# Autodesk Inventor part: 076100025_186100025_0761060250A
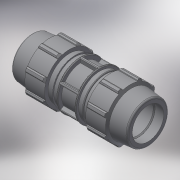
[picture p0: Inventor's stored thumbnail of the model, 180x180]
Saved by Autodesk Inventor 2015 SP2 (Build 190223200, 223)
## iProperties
Created: 2017-02
Part Number: 076100025_186100025_0761060250A
Material: Generic
Description: PLASSON REPAIR COUPLER 25
Document SubType Name: Modeling
Designer: KIM
Mass: 153.013 g
Surface Area: 383.34 cm^2
Volume: 153.013 cm^3
Density: 1 g/cm^3
Appearance: Default
Author: KIM
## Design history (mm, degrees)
derived "07610.ipt"
feature "Solid1::07610.ipt"
tag "TaggingFeature1"
body "Solid1"
other parameters: "d1" = 136, "d2" = 25, "d4" = 11.33333, "d5" = 19.42857, "d7" = 54, "d8" = 40.5, "d9" = 19.42857, "d11" = 3.48571, "d12" = 43.2, "d13" = 120 deg, "d14" = 37.5, "d15" = 10 deg, "d16" = 48.6, "d18" = 1.25, "d19" = 35 deg, "d20" = 17.5 deg, "d21" = 50.22, "d23" = 0, "d25" = 360 deg, "d27" = 1.08, "d33" = 0.5, "d34" = 2.7, "d36" = 0, "d37" = 0.5, "d38" = 0.5, "d40" = 360 deg, "d42" = 24.48, "d43" = 1.62, "d46" = 0.75, "d50" = 4.47429, "d51" = 43.2, "d_" = 25, "E_" = 54, "H_" = 136, "d49" = 12.43429
